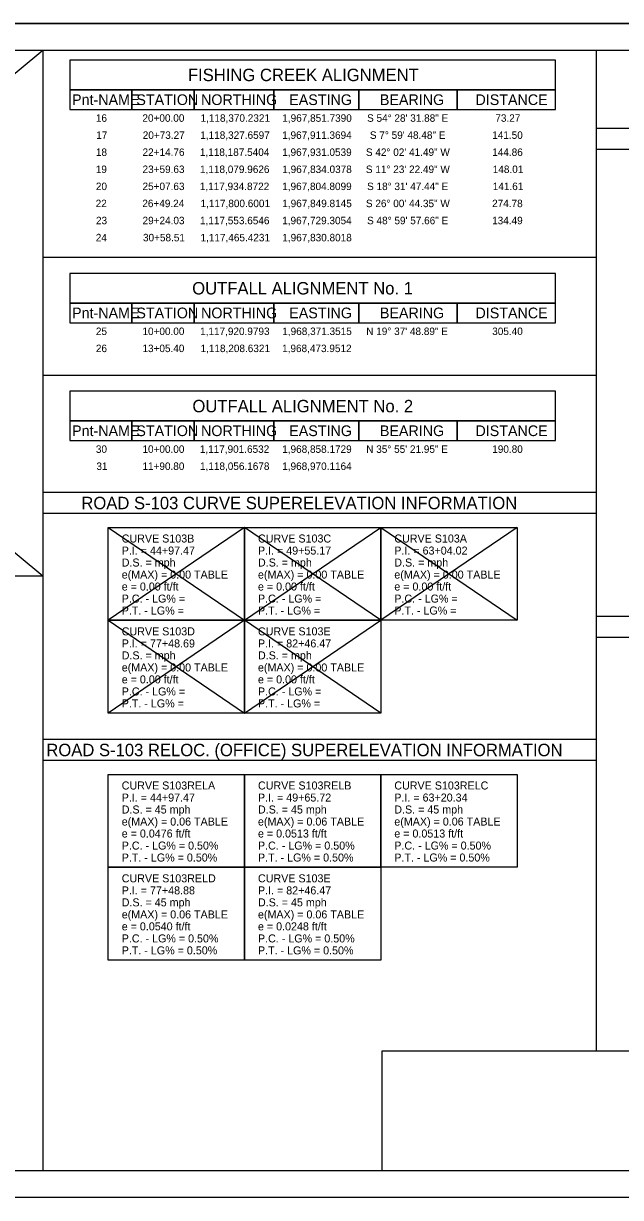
# Model space of a CAD drawing. Extents: x 8134 to 11793, y 3225 to 13425.
# Drawn here: x 10659 to 11218, y 4375 to 5475 of the extents above; entities that cross this region are included whole.
import ezdxf

# ---------------------------------------------------------------- set-up
doc = ezdxf.new("R2010")
doc.units = 0
for name, color, linetype in [('RD_SHT_Bndy', 7, 'Continuous'), ('RD_SHT_IplotShp', 7, 'Continuous'), ('RD_SHT_TX', 7, 'Continuous'), ('RD_TX_Misc1', 7, 'Continuous'), ('RD_TX_Misc2', 7, 'Continuous')]:
    doc.layers.add(name, color=color, linetype=linetype)

msp = doc.modelspace()

# ---------------------------------------------------------------- linework, layer by layer
at = {"layer": 'RD_SHT_Bndy'}
for p, q in [((11760, 5475), (10000, 5475)), ((11760, 5475), (10000, 5475)), ((10082.6, 5450), (10677.1, 4957.4)), ((10082.6, 4957.4), (10677.1, 5450)), ((10677.1, 5450), (10677.1, 4400)), ((11195.4, 5450), (11195.4, 4512.5)), ((10702.5, 5431.3), (10702.5, 5412.9)), ((10702.5, 5412.9), (10702.5, 5394.4)), ((10760.7, 5412.9), (10760.7, 5394.4)), ((11195.4, 5376.9), (11757.6, 5376.9)), ((11195.4, 5357.1), (11757.6, 5357.1)), ((10677.1, 5255.9), (11195.4, 5255.9)), ((10702.5, 5231.4), (10702.5, 5213)), ((10702.5, 5213), (10702.5, 5194.6)), ((10760.7, 5213), (10760.7, 5194.6)), ((10677.1, 5145.5), (11195.4, 5145.5)), ((10702.5, 5121), (10702.5, 5102.6)), ((10702.5, 5102.6), (10702.5, 5084.2)), ((10760.7, 5102.6), (10760.7, 5084.2)), ((10677.1, 5035.9), (11195.4, 5035.9)), ((10677.1, 5016.1), (11195.4, 5016.1)), ((10738.5, 5002.7), (10866.2, 4915.8)), ((10866.2, 5002.7), (10738.5, 4915.8)), ((10866.2, 4915.8), (10993.8, 5002.7)), ((10993.8, 4915.8), (10866.2, 5002.7)), ((10993.8, 5002.7), (11121.5, 4915.8)), ((11121.5, 5002.7), (10993.8, 4915.8)), ((10082.6, 4957.4), (10677.1, 4957.4)), ((11195.4, 4919.8), (11757.6, 4919.8)), ((10738.5, 4915.8), (10866.2, 4828.8)), ((10866.2, 4915.8), (10738.5, 4828.8)), ((10866.2, 4828.8), (10993.8, 4915.8)), ((10993.8, 4828.8), (10866.2, 4915.8)), ((11195.4, 4900), (11757.6, 4900)), ((10677.1, 4804.5), (11195.4, 4804.5)), ((10677.1, 4784.7), (11195.4, 4784.7)), ((10995, 4512.5), (11757.6, 4512.5)), ((10995, 4400), (10995, 4512.5)), ((11760, 4375), (10000, 4375)), ((11760, 4375), (10000, 4375))]:
    msp.add_line(p, q, dxfattribs=at)
for points in [[(10082.6, 5450), (11757.6, 5450), (11757.6, 4400), (10082.6, 4400)], [(10738.5, 5002.7), (10866.2, 5002.7), (10866.2, 4915.8), (10738.5, 4915.8)], [(10866.2, 5002.7), (10993.8, 5002.7), (10993.8, 4915.8), (10866.2, 4915.8)], [(10993.8, 5002.7), (11121.5, 5002.7), (11121.5, 4915.8), (10993.8, 4915.8)], [(10738.5, 4915.8), (10866.2, 4915.8), (10866.2, 4828.8), (10738.5, 4828.8)], [(10866.2, 4915.8), (10993.8, 4915.8), (10993.8, 4828.8), (10866.2, 4828.8)], [(10738.5, 4771.3), (10866.2, 4771.3), (10866.2, 4684.4), (10738.5, 4684.4)], [(10866.2, 4771.3), (10993.8, 4771.3), (10993.8, 4684.4), (10866.2, 4684.4)], [(10993.8, 4771.3), (11121.5, 4771.3), (11121.5, 4684.4), (10993.8, 4684.4)], [(10738.5, 4684.4), (10866.2, 4684.4), (10866.2, 4597.4), (10738.5, 4597.4)], [(10866.2, 4684.4), (10993.8, 4684.4), (10993.8, 4597.4), (10866.2, 4597.4)]]:
    msp.add_lwpolyline(points, close=True, dxfattribs=at)
at = {"layer": 'RD_SHT_IplotShp'}
msp.add_lwpolyline([(9981.4, 5475), (11777.4, 5475), (11777.4, 4375), (9981.4, 4375)], close=True, dxfattribs=at)
at = {"layer": 'RD_TX_Misc2'}
for points in [[(10702.5, 5412.9), (11157.4, 5412.9), (11157.4, 5440.7), (10702.5, 5440.7)], [(10702.5, 5394.4), (10760.7, 5394.4), (10760.7, 5412.9), (10702.5, 5412.9)], [(10760.7, 5394.4), (10818.9, 5394.4), (10818.9, 5412.9), (10760.7, 5412.9)], [(10818.9, 5394.4), (10893.6, 5394.4), (10893.6, 5412.9), (10818.9, 5412.9)], [(10893.6, 5394.4), (10973.1, 5394.4), (10973.1, 5412.9), (10893.6, 5412.9)], [(11065.3, 5412.9), (10973.1, 5412.9), (10973.1, 5394.4), (11065.3, 5394.4)], [(11157.4, 5412.9), (11065.3, 5412.9), (11065.3, 5394.4), (11157.4, 5394.4)], [(10702.5, 5213), (11157.4, 5213), (11157.4, 5240.9), (10702.5, 5240.9)], [(10702.5, 5194.6), (10760.7, 5194.6), (10760.7, 5213), (10702.5, 5213)], [(10760.7, 5194.6), (10818.9, 5194.6), (10818.9, 5213), (10760.7, 5213)], [(10818.9, 5194.6), (10893.6, 5194.6), (10893.6, 5213), (10818.9, 5213)], [(10893.6, 5194.6), (10973.1, 5194.6), (10973.1, 5213), (10893.6, 5213)], [(11065.3, 5213), (10973.1, 5213), (10973.1, 5194.6), (11065.3, 5194.6)], [(11157.4, 5213), (11065.3, 5213), (11065.3, 5194.6), (11157.4, 5194.6)], [(10702.5, 5102.6), (11157.4, 5102.6), (11157.4, 5130.5), (10702.5, 5130.5)], [(10702.5, 5084.2), (10760.7, 5084.2), (10760.7, 5102.6), (10702.5, 5102.6)], [(10760.7, 5084.2), (10818.9, 5084.2), (10818.9, 5102.6), (10760.7, 5102.6)], [(10818.9, 5084.2), (10893.6, 5084.2), (10893.6, 5102.6), (10818.9, 5102.6)], [(10893.6, 5084.2), (10973.1, 5084.2), (10973.1, 5102.6), (10893.6, 5102.6)], [(11065.3, 5102.6), (10973.1, 5102.6), (10973.1, 5084.2), (11065.3, 5084.2)], [(11157.4, 5102.6), (11065.3, 5102.6), (11065.3, 5084.2), (11157.4, 5084.2)]]:
    msp.add_lwpolyline(points, close=True, dxfattribs=at)

# ---------------------------------------------------------------- texts
at = {"layer": 'RD_SHT_TX'}
for s, height, p in [('16', 7, (10726.9, 5382.9)), ('20+00.00', 7, (10770.5, 5382.9)), ('1,118,370.2321', 7, (10824.9, 5382.9)), ('1,967,851.7390', 7, (10901.5, 5382.9)), ('S 54%%d 28\' 31.88" E', 7, (10980.9, 5382.9)), ('73.27', 7, (11101, 5382.9)), ('17', 7, (10727.2, 5366.9)), ('20+73.27', 7, (10770.8, 5366.9)), ('1,118,327.6597', 7, (10824.7, 5366.9)), ('1,967,911.3694', 7, (10901.4, 5366.9)), ('S 7%%d 59\' 48.48" E', 7, (10983.5, 5366.9)), ('141.50', 7, (11098.1, 5366.9)), ('18', 7, (10726.9, 5350.9)), ('22+14.76', 7, (10770.6, 5350.9)), ('1,118,187.5404', 7, (10824.3, 5350.9)), ('1,967,931.0539', 7, (10901.4, 5350.9)), ('S 42%%d 02\' 41.49" W', 7, (10979.8, 5350.9)), ('144.86', 7, (11098.1, 5350.9)), ('19', 7, (10726.8, 5334.9)), ('23+59.63', 7, (10770.6, 5334.9)), ('1,118,079.9626', 7, (10824.4, 5334.9)), ('1,967,834.0378', 7, (10901.5, 5334.9)), ('S 11%%d 23\' 22.49" W', 7, (10979.8, 5334.9)), ('148.01', 7, (11098.6, 5334.9)), ('20', 7, (10726.9, 5318.9)), ('25+07.63', 7, (10770.6, 5318.9)), ('1,117,934.8722', 7, (10824.2, 5318.9)), ('1,967,804.8099', 7, (10901.4, 5318.9)), ('S 18%%d 31\' 47.44" E', 7, (10980.9, 5318.9)), ('141.61', 7, (11098.6, 5318.9)), ('22', 7, (10726.7, 5302.9)), ('26+49.24', 7, (10770.4, 5302.9)), ('1,117,800.6001', 7, (10824.9, 5302.9)), ('1,967,849.8145', 7, (10901.5, 5302.9)), ('S 26%%d 00\' 44.35" W', 7, (10979.8, 5302.9)), ('274.78', 7, (11098, 5302.9)), ('23', 7, (10727, 5286.9)), ('29+24.03', 7, (10770.6, 5286.9)), ('1,117,553.6546', 7, (10824.4, 5286.9)), ('1,967,729.3054', 7, (10901.4, 5286.9)), ('S 48%%d 59\' 57.66" E', 7, (10980.9, 5286.9)), ('134.49', 7, (11098, 5286.9)), ('24', 7, (10726.8, 5270.9)), ('30+58.51', 7, (10771, 5270.9)), ('1,117,465.4231', 7, (10824.9, 5270.9)), ('1,967,830.8018', 7, (10901.5, 5270.9)), ('25', 7, (10726.9, 5183.1)), ('10+00.00', 7, (10770.5, 5183.1)), ('1,117,920.9793', 7, (10824.5, 5183.1)), ('1,968,371.3515', 7, (10901.5, 5183.1)), ('N 19%%d 37\' 48.89" E', 7, (10980.1, 5183.1)), ('305.40', 7, (11098.1, 5183.1)), ('26', 7, (10726.9, 5167.1)), ('13+05.40', 7, (10770.5, 5167.1)), ('1,118,208.6321', 7, (10824.9, 5167.1)), ('1,968,473.9512', 7, (10901.3, 5167.1)), ('30', 7, (10726.9, 5072.7)), ('10+00.00', 7, (10770.5, 5072.7)), ('1,117,901.6532', 7, (10824.2, 5072.7)), ('1,968,858.1729', 7, (10901.4, 5072.7)), ('N 35%%d 55\' 21.95" E', 7, (10980.1, 5072.7)), ('190.80', 7, (11098.1, 5072.7)), ('31', 7, (10727.4, 5056.7)), ('11+90.80', 7, (10770.5, 5056.7)), ('1,118,056.1678', 7, (10824.4, 5056.7)), ('1,968,970.1164', 7, (10901.4, 5056.7)), ('CURVE S103B', 7.5, (10751.1, 4988.7)), ('CURVE S103C', 7.5, (10878.7, 4988.7)), ('CURVE S103A', 7.5, (11006.4, 4988.7)), ('P.I. = 44+97.47', 7.5, (10751.1, 4977.4)), ('P.I. = 49+55.17', 7.5, (10878.7, 4977.4)), ('P.I. = 63+04.02', 7.5, (11006.4, 4977.4)), ('D.S. = mph', 7.5, (10751.1, 4966.2)), ('D.S. = mph', 7.5, (10878.7, 4966.2)), ('D.S. = mph', 7.5, (11006.4, 4966.2)), ('e(MAX) = 0.00 TABLE', 7.5, (10751.1, 4954.9)), ('e(MAX) = 0.00 TABLE', 7.5, (10878.7, 4954.9)), ('e(MAX) = 0.00 TABLE', 7.5, (11006.4, 4954.9)), ('e = 0.00 ft/ft', 7.5, (10751.1, 4943.7)), ('e = 0.00 ft/ft', 7.5, (10878.7, 4943.7)), ('e = 0.00 ft/ft', 7.5, (11006.4, 4943.7)), ('P.C. - LG% =', 7.5, (10751.1, 4932.4)), ('P.C. - LG% =', 7.5, (10878.7, 4932.4)), ('P.C. - LG% =', 7.5, (11006.4, 4932.4)), ('P.T. - LG% =', 7.5, (10751.1, 4921.2)), ('P.T. - LG% =', 7.5, (10878.7, 4921.2)), ('P.T. - LG% =', 7.5, (11006.4, 4921.2)), ('CURVE S103D', 7.5, (10751.1, 4901.7)), ('CURVE S103E', 7.5, (10878.7, 4901.7)), ('P.I. = 77+48.69', 7.5, (10751.1, 4890.4)), ('P.I. = 82+46.47', 7.5, (10878.7, 4890.4)), ('D.S. = mph', 7.5, (10751.1, 4879.2)), ('D.S. = mph', 7.5, (10878.7, 4879.2)), ('e(MAX) = 0.00 TABLE', 7.5, (10751.1, 4867.9)), ('e(MAX) = 0.00 TABLE', 7.5, (10878.7, 4867.9)), ('e = 0.00 ft/ft', 7.5, (10751.1, 4856.7)), ('e = 0.00 ft/ft', 7.5, (10878.7, 4856.7)), ('P.C. - LG% =', 7.5, (10751.1, 4845.4)), ('P.C. - LG% =', 7.5, (10878.7, 4845.4)), ('P.T. - LG% =', 7.5, (10751.1, 4834.2)), ('P.T. - LG% =', 7.5, (10878.7, 4834.2)), ('CURVE S103RELA', 7.5, (10751.1, 4757.3)), ('CURVE S103RELB', 7.5, (10878.7, 4757.3)), ('CURVE S103RELC', 7.5, (11006.4, 4757.3)), ('P.I. = 44+97.47', 7.5, (10751.1, 4746)), ('P.I. = 49+65.72', 7.5, (10878.7, 4746)), ('P.I. = 63+20.34', 7.5, (11006.4, 4746)), ('D.S. = 45 mph', 7.5, (10751.1, 4734.8)), ('D.S. = 45 mph', 7.5, (10878.7, 4734.8)), ('D.S. = 45 mph', 7.5, (11006.4, 4734.8)), ('e(MAX) = 0.06 TABLE', 7.5, (10751.1, 4723.5)), ('e(MAX) = 0.06 TABLE', 7.5, (10878.7, 4723.5)), ('e(MAX) = 0.06 TABLE', 7.5, (11006.4, 4723.5)), ('e = 0.0476 ft/ft', 7.5, (10751.1, 4712.3)), ('e = 0.0513 ft/ft', 7.5, (10878.7, 4712.3)), ('e = 0.0513 ft/ft', 7.5, (11006.4, 4712.3)), ('P.C. - LG% = 0.50%', 7.5, (10751.1, 4701)), ('P.C. - LG% = 0.50%', 7.5, (10878.7, 4701)), ('P.C. - LG% = 0.50%', 7.5, (11006.4, 4701)), ('P.T. - LG% = 0.50%', 7.5, (10751.1, 4689.8)), ('P.T. - LG% = 0.50%', 7.5, (10878.7, 4689.8)), ('P.T. - LG% = 0.50%', 7.5, (11006.4, 4689.8)), ('CURVE S103RELD', 7.5, (10751.1, 4670.3)), ('CURVE S103E', 7.5, (10878.7, 4670.3)), ('P.I. = 77+48.88', 7.5, (10751.1, 4659)), ('P.I. = 82+46.47', 7.5, (10878.7, 4659)), ('D.S. = 45 mph', 7.5, (10751.1, 4647.8)), ('D.S. = 45 mph', 7.5, (10878.7, 4647.8)), ('e(MAX) = 0.06 TABLE', 7.5, (10751.1, 4636.5)), ('e(MAX) = 0.06 TABLE', 7.5, (10878.7, 4636.5)), ('e = 0.0540 ft/ft', 7.5, (10751.1, 4625.3)), ('e = 0.0248 ft/ft', 7.5, (10878.7, 4625.3)), ('P.C. - LG% = 0.50%', 7.5, (10751.1, 4614)), ('P.C. - LG% = 0.50%', 7.5, (10878.7, 4614)), ('P.T. - LG% = 0.50%', 7.5, (10751.1, 4602.8)), ('P.T. - LG% = 0.50%', 7.5, (10878.7, 4602.8))]:
    msp.add_text(s, height=height, dxfattribs=at).set_placement(p)
at = {"layer": 'RD_TX_Misc1'}
for s, height, p in [('FISHING CREEK ALIGNMENT', 11.64, (10813.1, 5421)), ('Pnt-NAME', 10, (10704.6, 5398.6)), ('STATION', 10, (10764.8, 5398.6)), ('NORTHING', 10, (10825.4, 5398.6)), ('EASTING', 10, (10908, 5398.6)), ('BEARING', 10, (10992.9, 5398.6)), ('DISTANCE', 10, (11082.4, 5398.6)), ('OUTFALL ALIGNMENT No. 1', 11.64, (10817.1, 5221.1)), ('Pnt-NAME', 10, (10704.6, 5198.8)), ('STATION', 10, (10764.8, 5198.8)), ('NORTHING', 10, (10825.4, 5198.8)), ('EASTING', 10, (10908, 5198.8)), ('BEARING', 10, (10992.9, 5198.8)), ('DISTANCE', 10, (11082.4, 5198.8)), ('OUTFALL ALIGNMENT No. 2', 11.64, (10817.3, 5110.7)), ('Pnt-NAME', 10, (10704.6, 5088.4)), ('STATION', 10, (10764.8, 5088.4)), ('NORTHING', 10, (10825.4, 5088.4)), ('EASTING', 10, (10908, 5088.4)), ('BEARING', 10, (10992.9, 5088.4)), ('DISTANCE', 10, (11082.4, 5088.4)), ('ROAD S-103 CURVE SUPERELEVATION INFORMATION', 11.64, (10713.3, 5019.9)), ('ROAD S-103 RELOC. (OFFICE) SUPERELEVATION INFORMATION', 11.64, (10680.5, 4788.5))]:
    msp.add_text(s, height=height, dxfattribs=at).set_placement(p)

doc.saveas('drawing.dxf')
